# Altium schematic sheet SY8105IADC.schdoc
size 127 x 101 mm
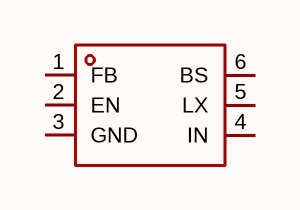
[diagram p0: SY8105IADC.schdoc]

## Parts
U?  sy8105iadc  [TSOT-23-6_L2.9-W1.6-P0.95-LS2.8-BR]  (value not drawn)

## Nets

Not connected (* = marked no-connect by the designer): U? 1(FB) 2(EN) 3(GND) 4(IN) 5(LX) 6(BS)

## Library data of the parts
U? = sy8105iadc: 功能类型:降压型;工作电压:4.5V~18V;输出电压:-;输出电流:5A;输出类型:可调;; Manufacturer: Silergy(矽力杰); AddInBom: yes; ModelId: 2c4039b5b88644c1bda4b4ba9e971667; ModelName: TSOT-23-6_L2.9-W1.6-H1.1-LS2.8-P0.95; ModelTransform: 110.45568,114.173,0,180,0,0,-0.005,-0.0005,0; Function: 降压型; Output Current: 5A; Frequency - Switching: 500kHz; Synchronous Rectifier: 是; Number of Outputs: 1; Topology: 降压式; Quiescent Current: 250uA; Switch tube (built-in/external): 内置; Output Type: 可调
